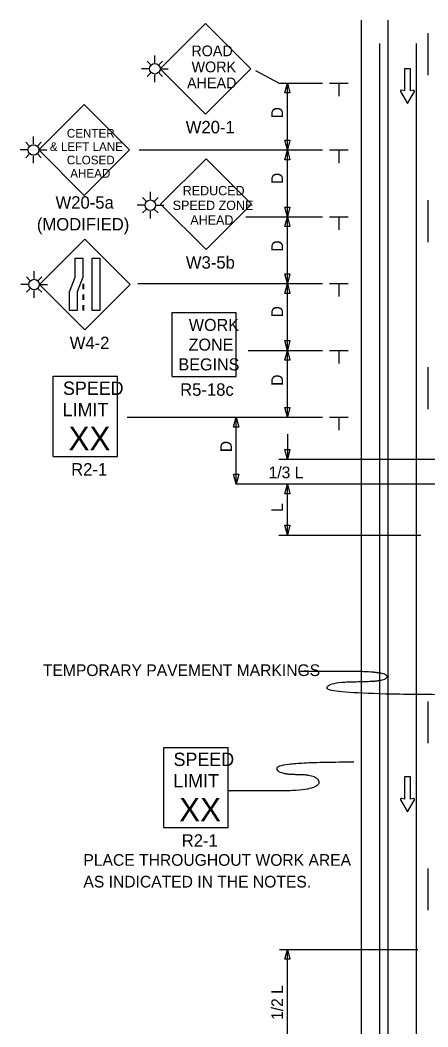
# Model space of a CAD drawing. Extents: x 16525 to 18475, y 5726 to 6926.
# Drawn here: x 16729 to 16973, y 6323 to 6926 of the extents above; entities that cross this region are included whole.
import ezdxf

# ---------------------------------------------------------------- set-up
doc = ezdxf.new("R2010")
doc.units = 0
for name, color, linetype in [('ALI_LEGAL_EX', 7, 'Continuous'), ('MT_SCRATCH_LEVEL_E', 7, 'Continuous'), ('PAVT_EDGE_EX', 7, 'Continuous'), ('TRAFFIC_SIGNS_PR', 7, 'Continuous'), ('TYPICAL_TEXT_DIMEN_PR', 7, 'Continuous')]:
    doc.layers.add(name, color=color, linetype=linetype)

msp = doc.modelspace()

# ---------------------------------------------------------------- linework, layer by layer
at = {"layer": 'ALI_LEGAL_EX'}
for points in [[(16973, 6918.24), (16973, 6893.24)], [(16973, 6818.24), (16973, 6793.24)], [(16973, 6818.24), (16973, 6793.24)], [(16973, 6718.24), (16973, 6693.24)], [(16973, 6718.24), (16973, 6693.24)], [(16973, 6518.24), (16973, 6493.24)], [(16973, 6518.24), (16973, 6493.24)], [(16973, 6418.24), (16973, 6393.24)], [(16973, 6418.24), (16973, 6393.24)]]:
    msp.add_lwpolyline(points, dxfattribs=at)
at = {"layer": 'MT_SCRATCH_LEVEL_E'}
for p, q in [((16962.67, 6897.03), (16958.93, 6897.03)), ((16958.93, 6897.03), (16958.93, 6883.77)), ((16962.67, 6897.03), (16958.93, 6897.03)), ((16958.93, 6897.03), (16958.93, 6883.77)), ((16962.67, 6883.77), (16962.67, 6897.03)), ((16962.67, 6883.77), (16962.67, 6897.03)), ((16956.67, 6883.4), (16960.82, 6876.16)), ((16956.67, 6883.4), (16960.82, 6876.16)), ((16958.93, 6883.77), (16957.15, 6884.09)), ((16958.93, 6883.77), (16957.15, 6884.09)), ((16960.82, 6876.16), (16964.93, 6883.4)), ((16960.82, 6876.16), (16964.93, 6883.4)), ((16964.44, 6884.09), (16962.67, 6883.77)), ((16964.44, 6884.09), (16962.67, 6883.77)), ((16962.67, 6473.03), (16958.93, 6473.03)), ((16958.93, 6473.03), (16958.93, 6459.77)), ((16962.67, 6473.03), (16958.93, 6473.03)), ((16958.93, 6473.03), (16958.93, 6459.77)), ((16962.67, 6459.77), (16962.67, 6473.03)), ((16962.67, 6459.77), (16962.67, 6473.03)), ((16956.67, 6459.4), (16960.82, 6452.16)), ((16956.67, 6459.4), (16960.82, 6452.16)), ((16958.93, 6459.77), (16957.15, 6460.09)), ((16958.93, 6459.77), (16957.15, 6460.09)), ((16960.82, 6452.16), (16964.93, 6459.4)), ((16960.82, 6452.16), (16964.93, 6459.4)), ((16964.44, 6460.09), (16962.67, 6459.77)), ((16964.44, 6460.09), (16962.67, 6459.77))]:
    msp.add_line(p, q, dxfattribs=at)
for centre, start, end in [((16957.08, 6883.63), 80.03619, 209.77312), ((16957.08, 6883.63), 80.03619, 209.77312), ((16964.52, 6883.63), 330.42484, 99.96381), ((16964.52, 6883.63), 330.42484, 99.96381), ((16957.08, 6459.63), 80.03619, 209.77312), ((16957.08, 6459.63), 80.03619, 209.77312), ((16964.52, 6459.63), 330.42484, 99.96381), ((16964.52, 6459.63), 330.42484, 99.96381)]:
    msp.add_arc(centre, 0.463, start, end, dxfattribs=at)
at = {"layer": 'PAVT_EDGE_EX'}
for p, q in [((16933, 6926.09), (16933, 6125.43)), ((16949, 6926.09), (16949, 6125.43)), ((16944.07, 6912.1), (16944.07, 6082.91)), ((16966.07, 6912.1), (16966.07, 6082.91))]:
    msp.add_line(p, q, dxfattribs=at)
at = {"layer": 'TRAFFIC_SIGNS_PR'}
for p, q in [((16839.93, 6924.13), (16812.74, 6896.95)), ((16867.12, 6896.95), (16839.93, 6924.13)), ((16807.08, 6899.46), (16804.97, 6901.57)), ((16809.59, 6900.5), (16809.59, 6905)), ((16812.1, 6899.46), (16814.21, 6901.57)), ((16806.44, 6896.95), (16801.6, 6896.95)), ((16812.74, 6896.95), (16817.63, 6896.95)), ((16812.74, 6896.95), (16839.93, 6869.76)), ((16839.93, 6869.76), (16867.12, 6896.95)), ((16807.08, 6894.44), (16804.97, 6892.33)), ((16809.59, 6888.98), (16809.59, 6893.39)), ((16812.1, 6894.44), (16814.21, 6892.33)), ((16767.32, 6875.53), (16740.13, 6848.35)), ((16794.5, 6848.35), (16767.32, 6875.53)), ((16734.46, 6850.86), (16732.36, 6852.97)), ((16736.98, 6851.9), (16736.98, 6856.4)), ((16739.49, 6850.86), (16741.6, 6852.97)), ((16733.82, 6848.35), (16728.99, 6848.35)), ((16740.13, 6848.35), (16745.01, 6848.35)), ((16740.13, 6848.35), (16767.32, 6821.16)), ((16767.32, 6821.16), (16794.5, 6848.35)), ((16734.46, 6845.84), (16732.36, 6843.73)), ((16736.98, 6840.38), (16736.98, 6844.79)), ((16739.49, 6845.84), (16741.6, 6843.73)), ((16840.23, 6843.07), (16813.08, 6815.92)), ((16867.38, 6815.92), (16840.23, 6843.07)), ((16806.92, 6818.83), (16806.92, 6823.33)), ((16804.41, 6817.79), (16802.3, 6819.9)), ((16809.44, 6817.79), (16811.55, 6819.9)), ((16803.77, 6815.28), (16798.93, 6815.28)), ((16804.41, 6812.76), (16802.3, 6810.66)), ((16806.92, 6807.31), (16806.92, 6811.72)), ((16809.44, 6812.76), (16811.54, 6810.66)), ((16810.08, 6815.28), (16814.96, 6815.28)), ((16813.08, 6815.92), (16840.23, 6788.76)), ((16840.23, 6788.76), (16867.38, 6815.92)), ((16767.7, 6794.91), (16740.55, 6767.76)), ((16794.85, 6767.76), (16767.7, 6794.91)), ((16737.36, 6771.35), (16737.36, 6775.85)), ((16734.84, 6770.3), (16732.74, 6772.41)), ((16739.87, 6770.3), (16741.98, 6772.41)), ((16766.45, 6768.25), (16766.45, 6765.05)), ((16766.85, 6768.25), (16766.85, 6765.05)), ((16734.2, 6767.79), (16729.37, 6767.79)), ((16734.84, 6765.28), (16732.74, 6763.17)), ((16737.36, 6759.83), (16737.36, 6764.24)), ((16739.87, 6765.28), (16741.98, 6763.17)), ((16740.51, 6767.79), (16745.39, 6767.79)), ((16740.55, 6767.76), (16767.7, 6740.6)), ((16767.7, 6740.6), (16794.85, 6767.76)), ((16766.45, 6761.85), (16766.45, 6758.65)), ((16766.85, 6761.85), (16766.85, 6758.65)), ((16766.45, 6755.45), (16766.45, 6752.25)), ((16766.85, 6755.45), (16766.85, 6752.25)), ((16819.94, 6712.66), (16819.94, 6751.06)), ((16819.94, 6751.06), (16858.34, 6751.06)), ((16858.34, 6712.66), (16858.34, 6751.06)), ((16748.84, 6712.88), (16787.24, 6712.88)), ((16748.84, 6664.88), (16748.84, 6712.88)), ((16787.24, 6664.88), (16787.24, 6712.88)), ((16819.94, 6712.66), (16858.34, 6712.66)), ((16748.84, 6664.88), (16787.24, 6664.88)), ((16815.03, 6490.7), (16853.43, 6490.7)), ((16815.03, 6442.7), (16815.03, 6490.7)), ((16853.43, 6442.7), (16853.43, 6490.7)), ((16815.03, 6442.7), (16853.43, 6442.7))]:
    msp.add_line(p, q, dxfattribs=at)
for points in [[(16766.45, 6783.49), (16766.45, 6772.31), (16763.11, 6763.43), (16763.11, 6752.25), (16758.61, 6752.25), (16758.61, 6763.43), (16761.96, 6772.31), (16761.96, 6783.49)], [(16776.59, 6783.49), (16776.59, 6752.25), (16772.09, 6752.25), (16772.09, 6783.49)]]:
    msp.add_lwpolyline(points, close=True, dxfattribs=at)
for centre in [(16809.59, 6896.95), (16736.98, 6848.35), (16806.92, 6815.28), (16737.36, 6767.79)]:
    msp.add_circle(centre, 3.15, dxfattribs=at)
at = {"layer": 'TYPICAL_TEXT_DIMEN_PR'}
for p, q in [((16883.9, 6888.35), (16870.07, 6895.77)), ((16883.9, 6888.35), (16909.9, 6888.35)), ((16887.33, 6882.49), (16888.9, 6888.35)), ((16888.9, 6848.35), (16888.9, 6888.35)), ((16888.9, 6888.35), (16890.47, 6882.49)), ((16914.15, 6888.35), (16925.4, 6888.35)), ((16919.78, 6888.35), (16919.78, 6880.56)), ((16888.9, 6882.49), (16887.33, 6882.49)), ((16890.47, 6882.49), (16888.9, 6882.49)), ((16888.9, 6848.35), (16887.33, 6854.21)), ((16887.33, 6854.21), (16888.9, 6854.21)), ((16888.9, 6854.21), (16890.47, 6854.21)), ((16890.47, 6854.21), (16888.9, 6848.35)), ((16800.23, 6848.35), (16909.9, 6848.35)), ((16883.9, 6848.35), (16909.9, 6848.35)), ((16887.33, 6842.49), (16888.9, 6848.35)), ((16888.9, 6808.35), (16888.9, 6848.35)), ((16888.9, 6848.35), (16890.47, 6842.49)), ((16914.15, 6848.35), (16925.4, 6848.35)), ((16919.78, 6848.35), (16919.78, 6840.56)), ((16888.9, 6842.49), (16887.33, 6842.49)), ((16890.47, 6842.49), (16888.9, 6842.49)), ((16888.9, 6808.35), (16887.33, 6814.21)), ((16887.33, 6814.21), (16888.9, 6814.21)), ((16888.9, 6814.21), (16890.47, 6814.21)), ((16890.47, 6814.21), (16888.9, 6808.35)), ((16864, 6808.35), (16909.9, 6808.35)), ((16883.9, 6808.35), (16909.9, 6808.35)), ((16887.33, 6802.49), (16888.9, 6808.35)), ((16888.9, 6808.35), (16890.47, 6802.49)), ((16888.9, 6768.35), (16888.9, 6808.35)), ((16914.15, 6808.35), (16925.4, 6808.35)), ((16919.78, 6808.35), (16919.78, 6800.56)), ((16888.9, 6802.49), (16887.33, 6802.49)), ((16890.47, 6802.49), (16888.9, 6802.49)), ((16888.9, 6768.35), (16887.33, 6774.21)), ((16887.33, 6774.21), (16888.9, 6774.21)), ((16888.9, 6774.21), (16890.47, 6774.21)), ((16890.47, 6774.21), (16888.9, 6768.35)), ((16799.33, 6768.35), (16909.9, 6768.35)), ((16883.9, 6768.35), (16909.9, 6768.35)), ((16887.33, 6762.49), (16888.9, 6768.35)), ((16888.9, 6768.35), (16890.47, 6762.49)), ((16888.9, 6728.35), (16888.9, 6768.35)), ((16914.15, 6768.35), (16925.4, 6768.35)), ((16919.78, 6768.35), (16919.78, 6760.56)), ((16888.9, 6762.49), (16887.33, 6762.49)), ((16890.47, 6762.49), (16888.9, 6762.49)), ((16888.9, 6728.35), (16887.33, 6734.21)), ((16887.33, 6734.21), (16888.9, 6734.21)), ((16888.9, 6734.21), (16890.47, 6734.21)), ((16890.47, 6734.21), (16888.9, 6728.35)), ((16865.52, 6728.35), (16909.9, 6728.35)), ((16887.33, 6722.49), (16888.9, 6728.35)), ((16888.9, 6728.35), (16890.47, 6722.49)), ((16888.9, 6688.35), (16888.9, 6728.35)), ((16914.15, 6728.35), (16925.4, 6728.35)), ((16919.78, 6728.35), (16919.78, 6720.56)), ((16888.9, 6722.49), (16887.33, 6722.49)), ((16890.47, 6722.49), (16888.9, 6722.49)), ((16888.9, 6688.35), (16887.33, 6694.21)), ((16887.33, 6694.21), (16888.9, 6694.21)), ((16888.9, 6694.21), (16890.47, 6694.21)), ((16890.47, 6694.21), (16888.9, 6688.35)), ((16793.05, 6688.35), (16909.9, 6688.35)), ((16856.75, 6682.49), (16858.32, 6688.35)), ((16858.32, 6688.35), (16859.89, 6682.49)), ((16858.32, 6648.35), (16858.32, 6688.35)), ((16914.15, 6688.35), (16925.4, 6688.35)), ((16919.78, 6688.35), (16919.78, 6680.56)), ((16858.32, 6682.49), (16856.75, 6682.49)), ((16859.89, 6682.49), (16858.32, 6682.49)), ((16888.9, 6678.19), (16888.9, 6663.27)), ((16888.9, 6663.27), (16887.33, 6669.13)), ((16887.33, 6669.13), (16888.9, 6669.13)), ((16888.9, 6669.13), (16890.47, 6669.13)), ((16890.47, 6669.13), (16888.9, 6663.27)), ((16883.9, 6663.27), (17013.03, 6663.27)), ((16858.32, 6648.35), (16856.75, 6654.21)), ((16856.75, 6654.21), (16858.32, 6654.21)), ((16858.32, 6654.21), (16859.89, 6654.21)), ((16859.89, 6654.21), (16858.32, 6648.35)), ((16989.81, 6648.35), (16858.32, 6648.35)), ((16887.33, 6642.49), (16888.9, 6648.35)), ((16888.9, 6617.81), (16888.9, 6648.35)), ((16888.9, 6648.35), (16890.47, 6642.49)), ((16888.9, 6642.49), (16887.33, 6642.49)), ((16890.47, 6642.49), (16888.9, 6642.49)), ((16888.9, 6617.81), (16887.33, 6623.68)), ((16887.33, 6623.68), (16888.9, 6623.68)), ((16888.9, 6623.68), (16890.47, 6623.68)), ((16890.47, 6623.68), (16888.9, 6617.81)), ((16883.9, 6617.81), (16968.72, 6617.81)), ((16884.27, 6369.82), (16966.99, 6369.82)), ((16887.33, 6363.96), (16888.9, 6369.82)), ((16888.9, 6369.82), (16890.47, 6363.96)), ((16888.9, 6311.18), (16888.9, 6369.82)), ((16888.9, 6363.96), (16887.33, 6363.96)), ((16890.47, 6363.96), (16888.9, 6363.96))]:
    msp.add_line(p, q, dxfattribs=at)
for points in [[(16997.4, 6522.18), (16912.62, 6522.18), (16912.62, 6530.06), (16948.58, 6530.06), (16948.58, 6536.21), (16900.28, 6536.21), (16896.35, 6536.21)], [(16928.65, 6481.83), (16882.56, 6481.83), (16882.56, 6474.56), (16907.74, 6474.56), (16907.74, 6464.65), (16858.09, 6464.65), (16853.16, 6464.65)]]:
    msp.add_open_spline(points, degree=2, dxfattribs=at)

# ---------------------------------------------------------------- texts
at = {"layer": 'TRAFFIC_SIGNS_PR'}
for s, height, p in [('ROAD', 6.408, (16831.46, 6904.49)), ('WORK', 6.408, (16831.57, 6894.88)), ('AHEAD', 6.408, (16828.88, 6885.27)), ('W20-1', 7.449, (16828.09, 6858.31)), ('CENTER', 5.206, (16756.94, 6855.76)), ('& LEFT LANE', 5.2065, (16746.8, 6847.75)), ('CLOSED', 5.206, (16756.94, 6839.74)), ('AHEAD', 5.206, (16758.97, 6831.73)), ('REDUCED', 5.6, (16826.29, 6821.23)), ('W20-5a', 7.449, (16750.16, 6813.22)), ('SPEED ZONE', 5.6, (16820.28, 6812.43)), ('(MODIFIED)', 7.449, (16739, 6800.16)), ('AHEAD', 5.6, (16830.84, 6803.63)), ('W3-5b', 7.44, (16828.18, 6777.32)), ('WORK', 7.217, (16829.94, 6740.02)), ('W4-2', 7.44, (16758.66, 6729.16)), ('ZONE', 7.217, (16829.82, 6728.21)), ('BEGINS', 7.217, (16823.74, 6716.4)), ('SPEED', 8, (16754.61, 6701.74)), ('R5-18c', 7.44, (16824.75, 6701.22)), ('LIMIT', 8, (16754.45, 6688.94)), ('XX', 14.031, (16757.96, 6668.64)), ('R2-1', 7.44, (16759.52, 6653.44)), ('SPEED', 8, (16820.8, 6479.56)), ('LIMIT', 8, (16820.64, 6466.76)), ('XX', 14.031, (16824.15, 6446.45)), ('R2-1', 7.44, (16825.71, 6431.26)), ('PLACE THROUGHOUT WORK AREA', 7, (16766.86, 6419.83)), ('AS INDICATED IN THE NOTES.', 7, (16766.86, 6406.83))]:
    msp.add_text(s, height=height, dxfattribs=at).set_placement(p)
at = {"layer": 'TYPICAL_TEXT_DIMEN_PR'}
for s, p in [('D', (16886.34, 6867.27)), ('D', (16886.34, 6827.94)), ('D', (16886.34, 6787.46)), ('D', (16886.34, 6748.13)), ('D', (16886.34, 6707.19)), ('D', (16855.76, 6667.42)), ('L', (16886.34, 6631.68)), ('1/2 L', (16886.34, 6327.55))]:
    msp.add_text(s, height=7, rotation=90, dxfattribs=at).set_placement(p)
for s, p in [('1/3 L', (16877.68, 6651.8)), ('TEMPORARY PAVEMENT MARKINGS', (16742.6, 6533.43))]:
    msp.add_text(s, height=7, dxfattribs=at).set_placement(p)

doc.saveas('drawing.dxf')
